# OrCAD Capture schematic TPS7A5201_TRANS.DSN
size Custom; title: TPS7A8300 2-A, 6-µVRMS, RF, LDO Voltage Regulator; rev: 1.0; note: DATASHEET:SBVS197E   EVM GUIDE: SBVU021
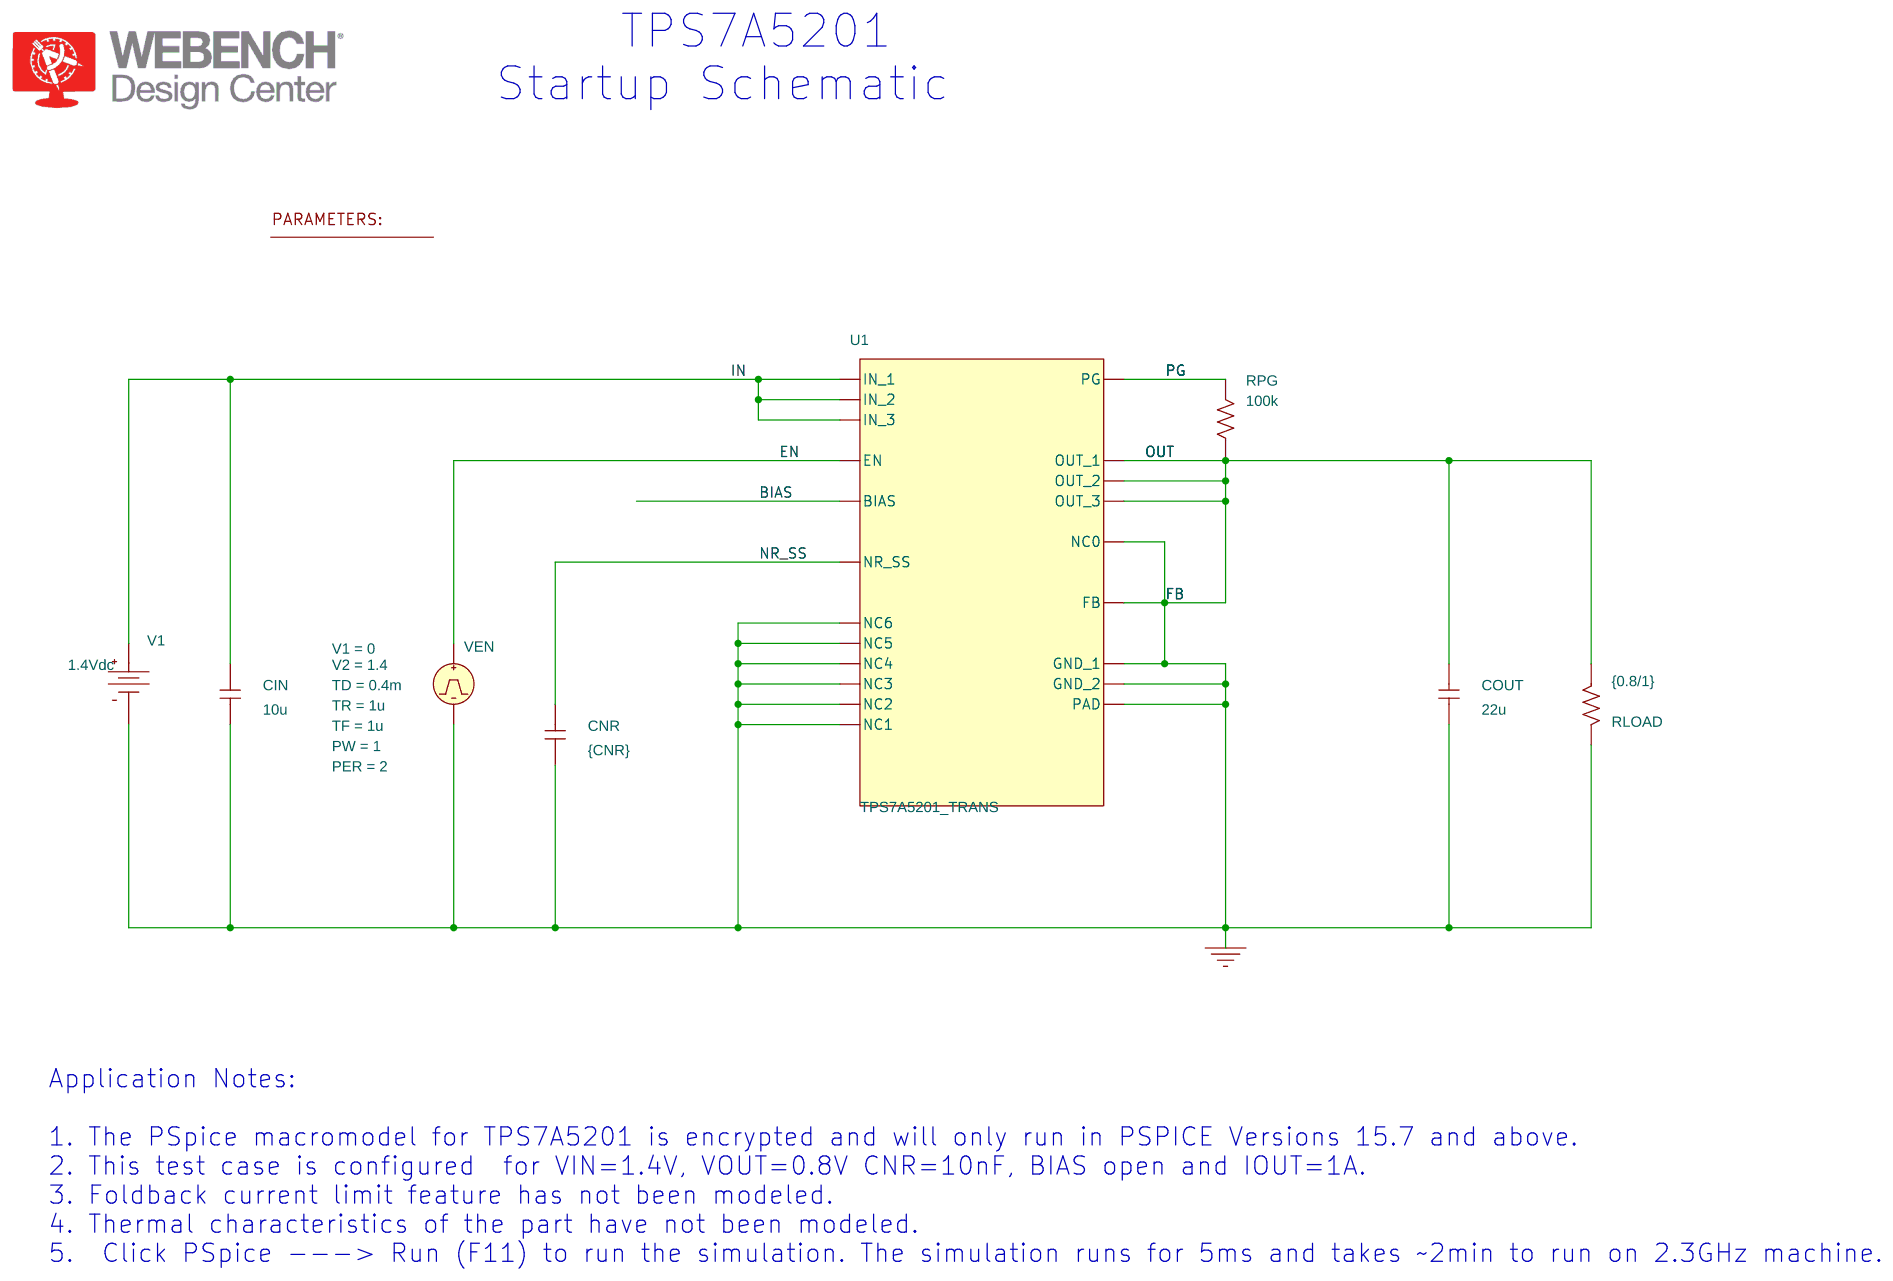
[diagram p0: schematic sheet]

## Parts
1  PARAM
CIN  10u  [RAD/CK05]
CNR  {CNR}  [RAD/CK05]
COUT  22u  [RAD/CK05]
RLOAD  {0.8/1}  [AX/RC05]
RPG  100k  [AX/RC05]
U1  TPS7A5201_TRANS
V1  VDC
VEN  VPULSE

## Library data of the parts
1 = PARAM: CNR: 10n
CIN COUT = C
CNR = C: IC: 0
RLOAD RPG = R
U1 = TPS7A5201_TRANS
V1 = VDC: DC: 1.4Vdc
VEN = VPULSE: PER: 2; PW: 1; TD: 0.4m; TF: 1u; TR: 1u; V1: 0; V2: 1.4

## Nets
0: CIN.1 CNR.1 COUT.1 RLOAD.2 U1.GND_1 U1.GND_2 U1.NC0 U1.NC1 U1.NC2 U1.NC3 U1.NC4 U1.NC5 U1.NC6 U1.PAD V1.1(-) VEN.2(-)
BIAS: U1.BIAS
EN: U1.EN VEN.1(+)
FB: COUT.2 RLOAD.1 RPG.1 U1.FB U1.OUT_1 U1.OUT_2 U1.OUT_3
IN: CIN.2 U1.IN_1 U1.IN_2 U1.IN_3 V1.0(+)
NR_SS: CNR.2 U1.NR_SS
PG: RPG.2 U1.PG

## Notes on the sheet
- TPS7A5201
  Startup Schematic
- Application Notes:
  1. The PSpice macromodel for TPS7A5201 is encrypted and will only run in PSPICE Versions 15.7 and above.
  2. This test case is configured  for VIN=1.4V, VOUT=0.8V CNR=10nF, BIAS open and IOUT=1A.
  3. Foldback current limit feature has not been modeled.
  4. Thermal characteristics of the part have not been modeled.
  5.  Click PSpice ---> Run (F11) to run the simulation. The simulation runs for 5ms and takes ~2min to run on 2.3GHz machine.
